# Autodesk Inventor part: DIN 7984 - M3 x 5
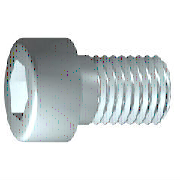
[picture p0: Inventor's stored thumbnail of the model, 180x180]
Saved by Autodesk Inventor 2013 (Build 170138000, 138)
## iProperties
IsCustomPart: 0
Created: 2012-02
Part Number: DIN 7984 - M3 x 5
Material: Stahl, weich
Description: Zylinderkopfschraube
Document SubType Name: Modeling
Standard: DIN 7984
Designer: rYan
Standard Revision: 1985
Standards Organization: DIN
Language: de-DE
Size Designation: M3 x 5
Categories: <MemberInstance><Categories><Category DisplayName="Verbindungselemente" InternalName="e4da775c-781d-43d5-af7c-5136215cf5a6" Mnemonic="FSTN"><Category DisplayNam
Density: 7.86 g/cm^3
Mass: 0.597673 g
Surface Area: 1.36052 cm^2
Volume: 0.0760398 cm^3
Author: rYan
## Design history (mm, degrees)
sketch "Skizze1"
  geometry: L1 (0.167, 0)-(5, 0); L2 (5, 0)-(5, 1.5); L3 (5, 1.5)-(1.5, 1.5); L4 (1.5, 1.5)-(1.193, 1.5); L5 (1.193, 1.5)-(0, 1.5); L6 (0, 1.5)-(0, 2.75); L7 (0, 2.75)-(-2, 2.75); L8 (-2, 2.75)-(-2, 1.155); L9 (-2, 1.155)-(-0.5, 1.155); L10 (-0.5, 1.155)-(0.167, 0); L11 (-3.4, 0)-(6.4, 0) reference; L12 (0, -0.55)-(0, 3.3) reference; L13 (1.5, 1.5)-(0, 1.5)
  constraints: 22 end point, 6 parallel, 2 collinear, 2 perpendicular, 1 horizontal, 1 point on line
  dimensions: "d1" = 3.5 distance from line of L3.end L2 (= GEL); "d2" = 0.30683 distance of L4.end L3.end (computed from GAL); "d3" = 2 distance between parallel lines of L8 L6 (= KOH); "d4" = 1.5 distance of L8.end L9.end (= INTI); "d5" = 60 deg angle of L10 L1; "d6" = 3 diameter of L3 L1 (= GD); "d7" = 3 diameter of L5 L1 (= BDM); "d8" = 2.3094 diameter of L9 L1 (= 1.1547 x SW); "d9" = 5.5 diameter of L7 L1 (= KOD); "d26" = 5 distance between parallel lines of L12 L2 (= NLG)
revolve "Körper" sketch "Skizze1" stored, may be unused: angle "d10" = 90 deg
sketch "Skizze2"
  geometry: L1 (0, -3.85)-(0, 3.85) reference; L2 (-3.85, 0)-(3.85, 0) reference; L3 (1.155, 0)-(0.577, -1); L4 (0.577, -1)-(-0.577, -1); L5 (-0.577, -1)-(-1.155, 0); L6 (-1.155, 0)-(-0.577, 1); L7 (-0.577, 1)-(0.577, 1); L8 (0.577, 1)-(1.155, 0); 2 further points
  constraints: 12 end point, 1 coincident, 1 horizontal alignment, 1 point on line, 12 other
extrude "Loch" join sketch "Skizze2" stored distance "d11" = 10; taper "d12" = 0 deg
workplane "Work Plane1"
fillet "Fillet2" dims "d30" = 0.1 (= R)
body "Solid1"
fillet "Rundung1" dims "d17" = 0.3 (= RR)
feature "Gewinde" dims "d13" = 3.5 (= GEL), "d14" = 0
chamfer "Fase1" distance "d15" = 0.30673 (= -0.5 x SPD + 0.5 x GD); stored, may be unused: second distance "d16" = 0.30673 (= GUL), angle "d27" = 45 deg
other parameters: "GD" = 3 (= NND) [user parameter; used in 2 equation terms], "NLG" = 5 [user parameter; used in 1 equation term], "GEL" = 3.5 [user parameter; used in 2 equation terms], "KOD" = 5.5 [user parameter; used in 1 equation term], "KOH" = 2 [user parameter; used in 1 equation term], "INTI" = 1.5 [user parameter; used in 1 equation term], "GAL" = 0.30673 (= 0.61345 x PTC) [user parameter; used in 1 equation term], "GUL" = 0.30673 (= 0.61345 x PTC) [user parameter; used in 1 equation term], "BDM" = 3 (= NND) [user parameter; used in 1 equation term], "SW" = 2 [user parameter; used in 2 equation terms], "RR" = 0.3 [user parameter; used in 1 equation term], "SPD" = 2.38655 (= NND - 1.2269 x PTC) [user parameter; used in 1 equation term], "d19" = 0, "d28" = 0, "d29" = 0, "R" = 0.1 [user parameter; used in 1 equation term], "TOA" = 30 deg [user parameter], "GD1" = 2.38655 (= THREADDIA - 1.2269 x PTC) [user parameter], "THREADDIA" = 3 [user parameter; used in 1 equation term], "FAWI" = 45 deg [user parameter], "ANG" = 120 deg [user parameter], "PTC" = 0.5 [user parameter; used in 5 equation terms], "NND" = 3 [user parameter; used in 3 equation terms], "E0" = 2.31 (= 1.155 x SW) [user parameter]
